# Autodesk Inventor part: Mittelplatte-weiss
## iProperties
Created: 2004-10
Part Number: Mittelplatte-weiss
Document SubType Name: Modeling
Designer: sahrens
Manufacturer: Standard
Standards Organization: Custom
Author: sahrens
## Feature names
1. Extrusion1
2. Extrusion2
3. Rundung2 [Fillet]
